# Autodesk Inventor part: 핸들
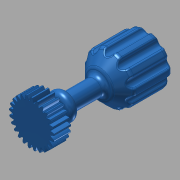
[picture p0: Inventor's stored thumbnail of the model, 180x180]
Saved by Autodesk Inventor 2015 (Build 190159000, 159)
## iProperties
Created: 2017-04
Part Number: 핸들
Material: 강철, 연강
Document SubType Name: Modeling
Designer: mduedu
Categories: <?xml version="1.0" encoding="UTF-16"?> <MemberInstance><Categories><FamilyTemplate><FamilyTemplateParameter ValueType="xs:double" Id="1" ObjectReferenceKey="da
Density: 7.86 g/cm^3
Appearance: 청록색
Mass: 193.539 g
Surface Area: 74.5308 cm^2
Volume: 24.6233 cm^3
CustomPartVersion: 1
Author: mduedu
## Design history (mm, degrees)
sketch "Sketch1"
  geometry: C1 r 13.5 at (0, 0)
  constraints: 1 centre point
  dimensions: "d0" = 27 diameter of C1 (= da_da)
extrude "Extrusion1" new body sketch "Sketch1" distance "d1" = 10 (= da_b); taper "d2" = 0 deg
workplane "Work Plane2"
sketch "Sketch2"
  geometry: C1 r 13.5 at (0, 0) reference; C2 r 12.5 at (0, 0)
  constraints: 1 centre point, 1 coincident
  dimensions: "d3" = 25 diameter of C2 (= da_dw)
feature "피치 지름" sketch "Sketch2" dims "d4" = 10, "d5" = 0
workplane "Work Plane8"
workplane "Work Plane9"
feature "스퍼 기어" dims "da_b" = 10, "da_d" = 25, "da_aw" = 25, "da_da" = 27, "da_df" = 22.5, "da_dw" = 25, angle "da_beta" = 0 deg, "da_lefttooth" = 0, "da_righttooth" = 0
sketch "스케치3"
  geometry: C1 r 5 at (0, 0); 1 further point
  constraints: 1 centre point, 1 coincident
  dimensions: "d49" = 10 diameter of C1
extrude "돌출2" join sketch "스케치3" distance "d50" = 60; taper "d51" = 0 deg
sketch "스케치4"
  geometry: C1 r 15 at (0, 0); 1 further point
  constraints: 1 centre point, 1 coincident
  dimensions: "d52" = 30 diameter of C1
extrude "돌출3" join sketch "스케치4" distance "d53" = 30; taper "d54" = 0 deg
chamfer "모따기1" distance "d55" = 7; stored, may be unused: second distance "d56" = 2, angle "d57" = 45 deg
sketch "스케치5"
  geometry: L1 (0, 2.2)-(0, -13.2) reference; L2 (0, -5)-(8, -5); L3 (8, -5)-(8, -11); L4 (8, -11)-(0, -11); L5 (0, -11)-(0, -5); 1 further point
  constraints: 8 end point, 2 parallel, 1 horizontal, 1 perpendicular, 1 point on line
  dimensions: "d58" = 5 distance from line of L2 point (0, 0); "d59" = 6 distance of L2.end L3.end; "d60" = 16 diameter of L3 L1
revolve "회전1" sketch "스케치5" stored, may be unused: angle "d61" = 90 deg
fillet "모깎기1" dims "d62" = 3
fillet "모깎기2" dims "d65" = 3
fillet "모깎기3" dims "d72" = 3
sketch "스케치6"
  geometry: C1 r 2.5 at (0, 15); 2 further points
  constraints: 2 vertical alignment, 1 centre point, 1 other
  dimensions: "d66" = 5 diameter of C1
extrude "돌출4" cut sketch "스케치6" stored distance "d67" = 35; taper "d68" = 0 deg
fillet "모깎기4" dims "d73" = 1
body "Solid1"
pattern_circular "원형 패턴2" dims angle "d75" = 360 deg
body "Srf1"
other parameters: "d16" = 25 (= da_aw), "d17" = 0, "d34" = 1.25664 (computed from da_z), "d39" = 0, "d41" = 0, "d43" = 25 (= da_aw), "d46" = 25 (= da_aw), "d47" = 0, "d48" = 0
